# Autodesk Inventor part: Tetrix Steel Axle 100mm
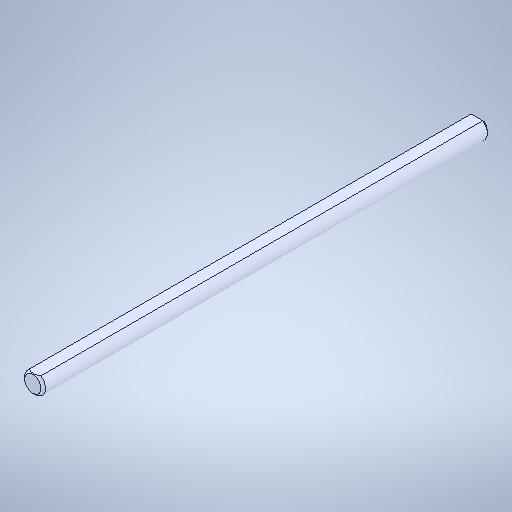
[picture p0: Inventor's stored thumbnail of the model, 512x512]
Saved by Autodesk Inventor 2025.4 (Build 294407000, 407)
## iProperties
Created: 2021-10
Part Number: Tetrix Steel Axle 100mm
Material: Genérico
Document SubType Name: Modeling
Designer: usuario
Density: 1 g/cm^3
Appearance: Valor por defecto
Author: usuario
Sending System: SolidWorks 2016
Last Author: LENOVO
Last Saved: 2021-10-22
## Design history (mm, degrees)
chamfer "Chamfer1"
node "Sólido1"
